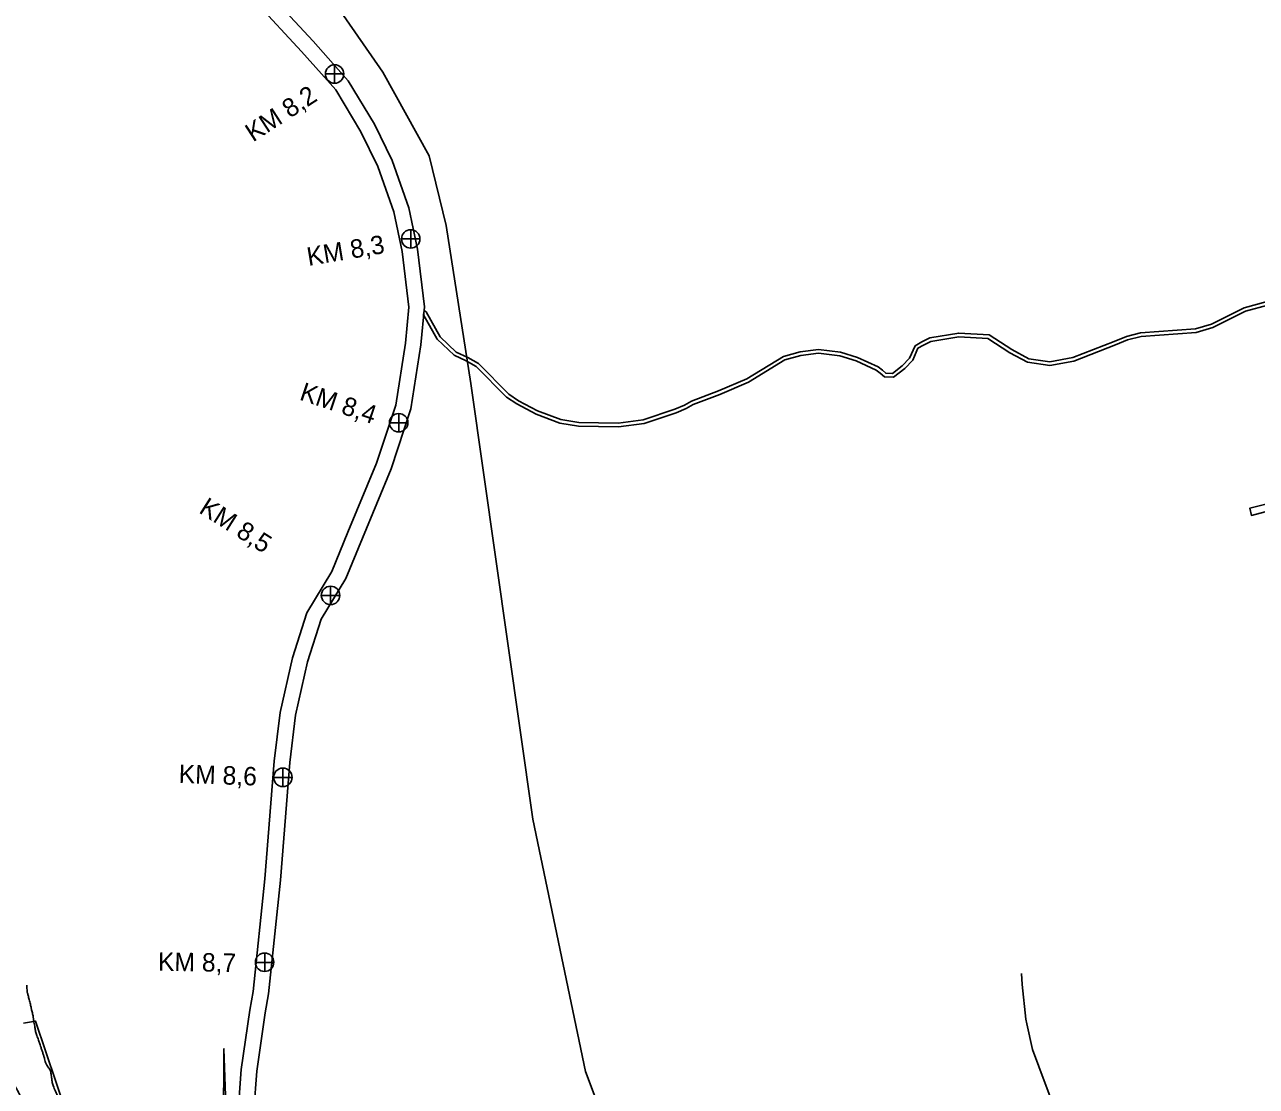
# Model space of a CAD drawing. Extents: x -478464 to -472469, y -1118040 to -1113785.
# Drawn here: x -476357 to -475690, y -1116872 to -1116297 of the extents above; entities that cross this region are included whole.
import ezdxf

# ---------------------------------------------------------------- set-up
doc = ezdxf.new("R2010")
doc.units = 0
for name, color, linetype in [('ObPÚ', 7, 'Continuous'), ('silnice', 7, 'Continuous'), ('staničení toku', 7, 'Continuous'), ('VAK_vodovod', 7, 'Continuous'), ('vodní plochy', 7, 'Continuous'), ('Vrstevnice_hlavni', 7, 'Continuous'), ('Vrstevnice_vedlejsi', 7, 'Continuous')]:
    doc.layers.add(name, color=color, linetype=linetype)

msp = doc.modelspace()

# ---------------------------------------------------------------- linework, layer by layer
at = {"layer": 'ObPÚ'}
for points in [[(-475631.84, -1116543.64), (-475693.15, -1116558.84), (-475692.22, -1116562.71), (-475661.8, -1116554.61)], [(-476326.63, -1116908.47), (-476339.71, -1116869.87), (-476350.95, -1116836.63), (-476357.4, -1116837.74)], [(-476247.65, -1116887.11), (-476248.8, -1116851.56), (-476249.04, -1116893.61)]]:
    msp.add_lwpolyline(points, dxfattribs=at)
at = {"layer": 'silnice'}
msp.add_lwpolyline([(-475903.982, -1117378.322), (-475889.519, -1117318.176), (-475888.389, -1117289.008), (-475895.395, -1117261.196), (-475916.638, -1117209.19), (-475969.886, -1117075.455), (-476021.05, -1116948.737), (-476052.923, -1116863.979), (-476081.44, -1116727.192), (-476114.99, -1116491.378), (-476128.411, -1116405.781), (-476137.637, -1116368.017), (-476162.8, -1116322.7), (-476200.543, -1116268.153), (-476239.965, -1116179.199), (-476260.934, -1116109.546), (-476288.613, -1116007.164), (-476289.451, -1115970.24), (-476274.354, -1115930.798), (-476261.922, -1115907.288), (-476366.595, -1115823.727)], dxfattribs=at)
at = {"layer": 'staničení toku'}
for p, q in [((-476188.887, -1116318.693), (-476188.887, -1116328.693)), ((-476183.887, -1116323.693), (-476193.887, -1116323.693)), ((-476142.632, -1116413.003), (-476152.632, -1116413.003)), ((-476147.632, -1116408.003), (-476147.632, -1116418.003)), ((-476154.16, -1116507.558), (-476154.16, -1116517.558)), ((-476149.16, -1116512.558), (-476159.16, -1116512.558)), ((-476186.071, -1116606.059), (-476196.071, -1116606.059)), ((-476191.071, -1116601.059), (-476191.071, -1116611.059)), ((-476216.904, -1116699.598), (-476216.904, -1116709.598)), ((-476211.904, -1116704.598), (-476221.904, -1116704.598)), ((-476226.63, -1116799.895), (-476226.63, -1116809.895)), ((-476221.63, -1116804.895), (-476231.63, -1116804.895))]:
    msp.add_line(p, q, dxfattribs=at)
for centre in [(-476188.887, -1116323.693), (-476147.632, -1116413.003), (-476154.16, -1116512.558), (-476191.071, -1116606.059), (-476216.904, -1116704.598), (-476226.814, -1116804.729)]:
    msp.add_circle(centre, 5, dxfattribs=at)
at = {"layer": 'VAK_vodovod'}
msp.add_lwpolyline([(-475764.07, -1116984.29), (-475764.159, -1116983.95), (-475770.76, -1116966.2), (-475773.519, -1116956.18), (-475773.699, -1116955.909), (-475773.909, -1116955.44), (-475773.98, -1116955.18), (-475782.599, -1116930.34), (-475789.389, -1116909.29), (-475792.36, -1116901.129), (-475795.449, -1116892.25), (-475795.679, -1116891.569), (-475801.449, -1116877.079), (-475803.873, -1116870.356), (-475810.739, -1116851.899), (-475813.889, -1116838.01), (-475814.349, -1116835.61), (-475816.44, -1116816.799), (-475816.731, -1116810.878)], dxfattribs=at)
at = {"layer": 'vodní plochy'}
for points in [[(-476232.54, -1116884.96), (-476231.056, -1116863.743), (-476226.487, -1116832.083), (-476224.65, -1116821.748), (-476218.166, -1116760.281), (-476213.201, -1116696.598), (-476209.998, -1116670.976), (-476203.505, -1116642.118), (-476196.126, -1116619.013), (-476182.743, -1116596.919), (-476173.799, -1116575.066), (-476158.205, -1116537.488), (-476147.489, -1116505.088), (-476142.144, -1116470.444), (-476140.228, -1116449.843), (-476143.996, -1116418.501), (-476148.705, -1116396.123), (-476157.644, -1116370.468), (-476167.296, -1116350.92), (-476181.445, -1116327.327), (-476200.558, -1116305.872), (-476225.178, -1116279.205)], [(-476231.457, -1116284.873), (-476206.824, -1116311.554), (-476188.29, -1116332.359), (-476174.728, -1116354.975), (-476165.46, -1116373.745), (-476156.871, -1116398.395), (-476152.35, -1116419.879), (-476148.734, -1116449.957), (-476150.542, -1116469.407), (-476155.741, -1116503.101), (-476166.138, -1116534.535), (-476181.62, -1116571.843), (-476190.32, -1116593.102), (-476203.88, -1116615.486), (-476211.676, -1116639.899), (-476218.341, -1116669.52), (-476221.619, -1116695.744), (-476226.591, -1116759.508), (-476233.031, -1116820.563), (-476234.839, -1116830.738), (-476239.473, -1116862.842), (-476241.054, -1116885.449)], [(-475683.608, -1116446.891), (-475696.084, -1116450.304), (-475713.807, -1116459.166), (-475722.473, -1116461.738), (-475752.339, -1116463.951), (-475759.965, -1116465.787), (-475766.557, -1116468.482), (-475788.947, -1116477.312), (-475801.381, -1116479.523), (-475812.887, -1116477.879), (-475821.999, -1116472.906), (-475834.317, -1116464.881), (-475850.769, -1116464.015), (-475866.412, -1116466.645), (-475870.757, -1116468.713), (-475874.45, -1116470.846), (-475877.363, -1116477.6), (-475881.336, -1116481.661), (-475886.708, -1116485.855), (-475890.269, -1116485.746), (-475892.098, -1116484.147), (-475894.417, -1116482.341), (-475905.696, -1116477.223), (-475914.798, -1116474.293), (-475926.788, -1116472.876), (-475936.751, -1116474.218), (-475945.782, -1116476.716), (-475965.569, -1116488.784), (-475980.889, -1116495.327), (-475995.516, -1116500.833), (-475999.401, -1116503.085), (-476004.548, -1116505.283), (-476021.706, -1116511.065), (-476035.253, -1116512.736), (-476056.535, -1116512.362), (-476066.322, -1116510.884), (-476078.941, -1116506.058), (-476089.177, -1116500.614), (-476094.447, -1116497.102), (-476110.893, -1116480.408), (-476116.755, -1116477.223), (-476122.949, -1116474.265), (-476131.753, -1116466.076), (-476139.274, -1116452.519), (-476140.406, -1116451.764)], [(-476140.406, -1116451.764), (-476140.632, -1116454.194)], [(-476140.632, -1116454.194), (-476133.347, -1116467.324), (-476124.087, -1116475.937), (-476117.665, -1116479.005), (-476112.109, -1116482.024), (-476095.727, -1116498.652), (-476090.203, -1116502.334), (-476079.771, -1116507.882), (-476066.834, -1116512.83), (-476056.703, -1116514.36), (-476035.147, -1116514.738), (-476021.26, -1116513.025)], [(-476021.26, -1116513.025), (-476003.834, -1116507.153), (-475998.503, -1116504.877), (-475994.656, -1116502.647), (-475980.143, -1116497.183), (-475964.651, -1116490.566), (-475944.98, -1116478.57), (-475936.349, -1116476.182), (-475926.772, -1116474.892), (-475915.226, -1116476.257), (-475906.418, -1116479.091), (-475895.459, -1116484.065), (-475893.372, -1116485.689), (-475891.047, -1116487.724), (-475886.046, -1116487.877), (-475880, -1116483.155), (-475875.673, -1116478.734), (-475872.876, -1116472.246), (-475869.825, -1116470.485), (-475865.804, -1116468.571), (-475850.655, -1116466.023), (-475834.959, -1116466.849), (-475823.025, -1116474.624), (-475813.527, -1116479.807), (-475801.347, -1116481.549), (-475788.399, -1116479.246), (-475765.811, -1116470.338), (-475759.349, -1116467.695), (-475752.029, -1116465.933), (-475722.111, -1116463.716), (-475713.069, -1116461.034), (-475695.366, -1116452.182), (-475683.312, -1116448.883)]]:
    msp.add_lwpolyline(points, dxfattribs=at)
at = {"layer": 'Vrstevnice_hlavni'}
msp.add_spline([(-476290.451, -1117027.093), (-476294.143, -1117019.711), (-476295.785, -1117015.473), (-476297.225, -1117010.687), (-476298.462, -1117005.353), (-476299.607, -1116999.86), (-476300.661, -1116994.209), (-476301.625, -1116988.399), (-476304.202, -1116983.42), (-476308.392, -1116979.272), (-476314.196, -1116975.955), (-476318.65, -1116972.632), (-476321.754, -1116969.303), (-476323.508, -1116965.967), (-476324.727, -1116963.134), (-476325.411, -1116960.803), (-476325.559, -1116958.974), (-476326.153, -1116954.193), (-476327.192, -1116946.457), (-476328.676, -1116935.769), (-476330.178, -1116927.048), (-476331.699, -1116920.295), (-476333.238, -1116915.511), (-476334.228, -1116912.248), (-476334.669, -1116910.507), (-476334.561, -1116910.289), (-476334.608, -1116910.078), (-476334.809, -1116909.875), (-476335.165, -1116909.68), (-476335.456, -1116909.362), (-476335.682, -1116908.921), (-476335.843, -1116908.358), (-476336.083, -1116907.957), (-476336.401, -1116907.719), (-476336.798, -1116907.644), (-476337.425, -1116907.127), (-476338.283, -1116906.169), (-476339.372, -1116904.768), (-476340.188, -1116903.766), (-476340.73, -1116903.163), (-476341, -1116902.958), (-476341.173, -1116902.778), (-476341.249, -1116902.623), (-476341.229, -1116902.494), (-476341.387, -1116901.345), (-476341.725, -1116899.176), (-476342.241, -1116895.988), (-476343.602, -1116892.958), (-476345.809, -1116890.086), (-476348.861, -1116887.372), (-476351.569, -1116884.909), (-476353.934, -1116882.696), (-476355.955, -1116880.733), (-476357.527, -1116879.066), (-476358.651, -1116877.694), (-476359.325, -1116876.618), (-476360.366, -1116874.804), (-476361.771, -1116872.252), (-476363.543, -1116868.962), (-476364.79, -1116866.693), (-476365.512, -1116865.444), (-476365.711, -1116865.215), (-476366.4, -1116863.614), (-476367.582, -1116860.642), (-476369.254, -1116856.299), (-476370.874, -1116852.253), (-476372.442, -1116848.505), (-476373.957, -1116845.055), (-476374.102, -1116840.913), (-476372.876, -1116836.079), (-476370.28, -1116830.553), (-476368.388, -1116825.744), (-476367.199, -1116821.652), (-476366.761, -1116818.75)], degree=3, dxfattribs=at)
at = {"layer": 'Vrstevnice_vedlejsi'}
for points in [[(-476355.598, -1116817.14), (-476355.598, -1116817.462), (-476355.522, -1116819.008), (-476355.435, -1116820.195), (-476355.338, -1116821.024), (-476355.232, -1116821.496), (-476355.045, -1116822.209), (-476354.778, -1116823.163), (-476354.431, -1116824.358), (-476354.109, -1116825.579), (-476353.811, -1116826.827), (-476353.538, -1116828.1), (-476353.336, -1116829.048), (-476353.204, -1116829.673), (-476353.144, -1116829.972), (-476352.999, -1116830.589), (-476352.77, -1116831.522), (-476352.458, -1116832.773), (-476352.235, -1116833.783), (-476352.101, -1116834.551), (-476352.056, -1116835.078), (-476351.935, -1116835.941), (-476351.739, -1116837.138), (-476351.466, -1116838.67), (-476351.232, -1116840.02), (-476351.037, -1116841.186), (-476350.88, -1116842.169), (-476350.603, -1116843.249), (-476350.205, -1116844.425), (-476349.687, -1116845.699), (-476349.242, -1116846.869), (-476348.872, -1116847.935), (-476348.576, -1116848.897), (-476348.165, -1116850.177), (-476347.641, -1116851.773), (-476347.002, -1116853.687), (-476346.456, -1116855.431), (-476346.002, -1116857.007), (-476345.642, -1116858.413), (-476345.115, -1116859.74), (-476344.421, -1116860.989), (-476343.561, -1116862.159), (-476342.957, -1116863.169), (-476342.608, -1116864.019), (-476342.514, -1116864.708), (-476342.372, -1116865.794), (-476342.181, -1116867.276), (-476341.941, -1116869.155), (-476341.252, -1116871.564), (-476340.114, -1116874.502), (-476338.527, -1116877.97), (-476336.854, -1116881.482), (-476335.094, -1116885.037), (-476333.247, -1116888.636), (-476331.659, -1116891.702), (-476330.328, -1116894.233), (-476329.256, -1116896.231), (-476328.529, -1116897.582), (-476328.146, -1116898.284), (-476328.108, -1116898.339), (-476327.898, -1116898.789), (-476327.518, -1116899.634), (-476326.967, -1116900.875), (-476326.567, -1116901.767), (-476326.32, -1116902.31), (-476326.226, -1116902.503), (-476326.057, -1116902.7), (-476325.813, -1116902.899), (-476325.496, -1116903.102), (-476325.106, -1116903.427), (-476324.643, -1116903.877), (-476324.106, -1116904.449), (-476323.564, -1116905.01), (-476323.015, -1116905.558), (-476322.46, -1116906.094), (-476321.647, -1116906.6), (-476320.578, -1116907.074), (-476319.251, -1116907.518), (-476317.806, -1116907.987), (-476316.243, -1116908.48)], [(-476312.721, -1117085.051), (-476312.162, -1117082.526), (-476311.913, -1117080.032), (-476311.974, -1117077.572), (-476312.345, -1117075.143), (-476313.383, -1117069.89), (-476315.09, -1117061.81), (-476317.464, -1117050.905), (-476319.053, -1117043.623), (-476319.857, -1117039.964), (-476319.875, -1117039.928), (-476319.898, -1117039.853), (-476319.928, -1117039.738), (-476319.964, -1117039.583), (-476320.808, -1117035.51), (-476322.459, -1117027.518), (-476324.918, -1117015.607), (-476326.714, -1117006.768), (-476327.848, -1117001), (-476328.319, -1116998.302), (-476330.077, -1116993.758), (-476333.121, -1116987.367), (-476337.453, -1116979.13), (-476340.546, -1116971.115), (-476342.399, -1116963.323), (-476343.014, -1116955.754), (-476343.66, -1116949.008), (-476344.337, -1116943.083), (-476345.046, -1116937.98), (-476345.79, -1116933.735), (-476346.568, -1116930.347), (-476347.382, -1116927.816), (-476347.813, -1116924.716), (-476347.859, -1116921.047), (-476347.522, -1116916.807), (-476347.291, -1116913.836), (-476347.165, -1116912.134), (-476347.145, -1116911.7), (-476347.131, -1116911.361), (-476347.123, -1116911.118), (-476347.12, -1116910.97), (-476347.358, -1116910.697), (-476347.835, -1116910.299), (-476348.553, -1116909.776), (-476349.688, -1116908.928), (-476351.241, -1116907.756), (-476353.21, -1116906.259), (-476354.451, -1116904.808), (-476354.966, -1116903.404), (-476354.753, -1116902.045), (-476354.661, -1116900.831), (-476354.691, -1116899.761), (-476354.84, -1116898.834), (-476355.497, -1116897.722), (-476356.66, -1116896.423), (-476358.33, -1116894.938), (-476360.327, -1116893.159), (-476362.652, -1116891.085), (-476365.304, -1116888.717), (-476367.486, -1116886.651), (-476369.2, -1116884.887), (-476370.445, -1116883.425), (-476371.635, -1116881.781), (-476372.771, -1116879.956), (-476373.852, -1116877.948), (-476374.758, -1116876.395), (-476375.49, -1116875.297), (-476376.047, -1116874.654), (-476377.319, -1116871.886), (-476379.306, -1116866.993), (-476382.008, -1116859.976), (-476384.043, -1116854.77), (-476385.41, -1116851.374), (-476386.109, -1116849.788), (-476386.823, -1116848.113), (-476387.55, -1116846.349), (-476388.291, -1116844.496), (-476388.743, -1116843.138), (-476388.908, -1116842.272), (-476388.783, -1116841.901), (-476388.764, -1116840.286), (-476388.848, -1116837.428), (-476389.037, -1116833.326), (-476388.798, -1116828.049), (-476388.13, -1116821.599), (-476388.122, -1116821.535)]]:
    msp.add_spline(points, degree=3, dxfattribs=at)

# ---------------------------------------------------------------- texts
at = {"layer": 'staničení toku'}
for s, rotation, p in [('KM 8,2', 32.985937, (-476233.061, -1116360.799)), ('KM 8,3', 9.563856, (-476203.002, -1116427.653)), ('KM 8,4', 341.522575, (-476208.422, -1116499.941)), ('KM 8,5', 327.636986, (-476262.92, -1116560.953)), ('KM 8,6', 358.042465, (-476273.456, -1116707.603)), ('KM 8,7', 359.051273, (-476284.619, -1116809.324))]:
    msp.add_text(s, height=10, rotation=rotation, dxfattribs=at).set_placement(p)

doc.saveas('drawing.dxf')
